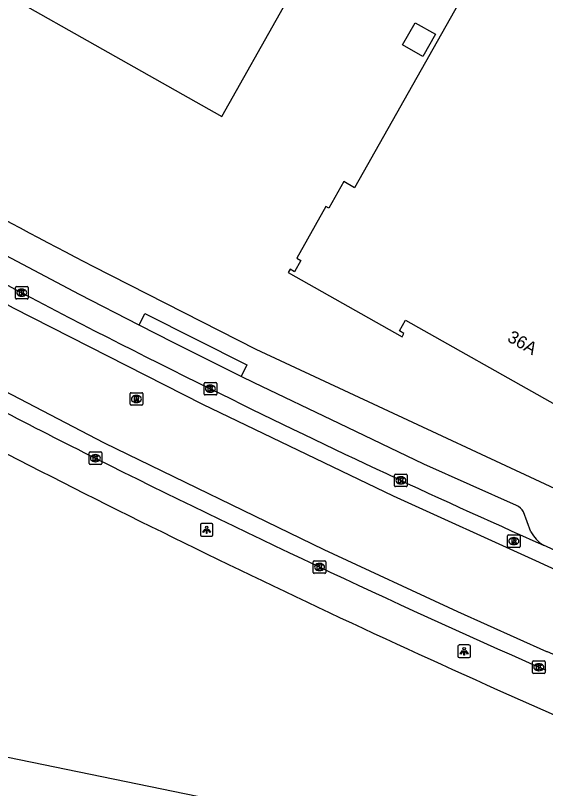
# Model space of a CAD drawing. Extents: x 157692 to 159670, y 381454 to 383289.
# Drawn here: x 158086.3 to 158128.6, y 382784.5 to 382846.1 of the extents above; entities that cross this region are included whole.
import ezdxf

# ---------------------------------------------------------------- set-up
doc = ezdxf.new("R2010")
doc.units = 0
for name, color, linetype in [('IMGEO_Kolk', 7, 'Continuous'), ('IMGEO_Lage_trafo', 7, 'Continuous'), ('IMGEO_Lichtpunt', 7, 'Continuous'), ('IMGEO_Pand', 7, 'Continuous'), ('IMGEO_Pand_nummerreeks', 7, 'Continuous'), ('IMGEO_Rijbaan_lokaal_gesloten', 7, 'Continuous'), ('IMGEO_Rioolput', 7, 'Continuous'), ('IMGEO_Voetpad_open', 7, 'Continuous')]:
    doc.layers.add(name, color=color, linetype=linetype)

msp = doc.modelspace()

# ---------------------------------------------------------------- linework, layer by layer
at = {"layer": 'IMGEO_Kolk'}
for p, q in [((158086.342, 382823.554), (158086.342, 382824.406)), ((158086.417, 382824.48), (158087.269, 382824.48)), ((158087.343, 382824.406), (158087.343, 382823.554)), ((158086.83, 382824.26), (158086.855, 382824.26)), ((158087.269, 382823.48), (158086.417, 382823.48)), ((158086.853, 382823.7), (158086.828, 382823.7)), ((158101.372, 382815.913), (158101.372, 382816.765)), ((158101.447, 382816.839), (158102.299, 382816.839)), ((158101.86, 382816.619), (158101.885, 382816.619)), ((158102.373, 382816.765), (158102.373, 382815.913)), ((158102.299, 382815.839), (158101.447, 382815.839)), ((158101.883, 382816.059), (158101.858, 382816.059)), ((158092.209, 382810.382), (158092.209, 382811.234)), ((158092.284, 382811.308), (158093.136, 382811.308)), ((158092.697, 382811.088), (158092.722, 382811.088)), ((158093.21, 382811.234), (158093.21, 382810.382)), ((158093.136, 382810.308), (158092.284, 382810.308)), ((158092.72, 382810.528), (158092.695, 382810.528)), ((158116.546, 382808.615), (158116.546, 382809.467)), ((158116.621, 382809.541), (158117.473, 382809.541)), ((158117.034, 382809.321), (158117.059, 382809.321)), ((158117.547, 382809.467), (158117.547, 382808.615)), ((158117.473, 382808.541), (158116.621, 382808.541)), ((158117.057, 382808.761), (158117.032, 382808.761)), ((158110.067, 382801.715), (158110.067, 382802.567)), ((158110.142, 382802.641), (158110.994, 382802.641)), ((158110.555, 382802.421), (158110.58, 382802.421)), ((158111.068, 382802.567), (158111.068, 382801.715)), ((158110.994, 382801.641), (158110.142, 382801.641)), ((158110.578, 382801.861), (158110.553, 382801.861)), ((158127.53, 382793.741), (158127.53, 382794.593)), ((158127.605, 382794.667), (158128.457, 382794.667)), ((158128.018, 382794.447), (158128.043, 382794.447)), ((158128.531, 382794.593), (158128.531, 382793.741)), ((158128.457, 382793.667), (158127.605, 382793.667)), ((158128.041, 382793.887), (158128.016, 382793.887))]:
    msp.add_line(p, q, dxfattribs=at)
for points in [[(158086.342, 382823.554), (158086.342, 382824.406)], [(158086.417, 382824.48), (158087.269, 382824.48)], [(158087.343, 382824.406), (158087.343, 382823.554)], [(158086.663, 382824.18), (158086.786, 382824.18), (158086.786, 382824.029), (158086.916, 382824.18), (158087.08, 382824.18), (158086.934, 382824.029), (158087.087, 382823.78), (158086.935, 382823.78), (158086.85, 382823.944), (158086.786, 382823.877), (158086.786, 382823.78), (158086.663, 382823.78), (158086.663, 382824.18)], [(158087.269, 382823.48), (158086.417, 382823.48)], [(158101.372, 382815.913), (158101.372, 382816.765)], [(158101.447, 382816.839), (158102.299, 382816.839)], [(158101.693, 382816.539), (158101.816, 382816.539), (158101.816, 382816.388), (158101.946, 382816.539), (158102.11, 382816.539), (158101.964, 382816.388), (158102.117, 382816.139), (158101.965, 382816.139), (158101.88, 382816.303), (158101.816, 382816.236), (158101.816, 382816.139), (158101.693, 382816.139), (158101.693, 382816.539)], [(158102.373, 382816.765), (158102.373, 382815.913)], [(158102.299, 382815.839), (158101.447, 382815.839)], [(158092.209, 382810.382), (158092.209, 382811.234)], [(158092.284, 382811.308), (158093.136, 382811.308)], [(158092.53, 382811.008), (158092.653, 382811.008), (158092.653, 382810.857), (158092.783, 382811.008), (158092.947, 382811.008), (158092.801, 382810.857), (158092.954, 382810.608), (158092.802, 382810.608), (158092.717, 382810.772), (158092.653, 382810.705), (158092.653, 382810.608), (158092.53, 382810.608), (158092.53, 382811.008)], [(158093.21, 382811.234), (158093.21, 382810.382)], [(158093.136, 382810.308), (158092.284, 382810.308)], [(158116.546, 382808.615), (158116.546, 382809.467)], [(158116.621, 382809.541), (158117.473, 382809.541)], [(158116.867, 382809.241), (158116.99, 382809.241), (158116.99, 382809.09), (158117.12, 382809.241), (158117.284, 382809.241), (158117.138, 382809.09), (158117.291, 382808.841), (158117.139, 382808.841), (158117.054, 382809.005), (158116.99, 382808.938), (158116.99, 382808.841), (158116.867, 382808.841), (158116.867, 382809.241)], [(158117.547, 382809.467), (158117.547, 382808.615)], [(158117.473, 382808.541), (158116.621, 382808.541)], [(158110.067, 382801.715), (158110.067, 382802.567)], [(158110.142, 382802.641), (158110.994, 382802.641)], [(158110.388, 382802.341), (158110.511, 382802.341), (158110.511, 382802.19), (158110.641, 382802.341), (158110.805, 382802.341), (158110.659, 382802.19), (158110.812, 382801.941), (158110.66, 382801.941), (158110.575, 382802.105), (158110.511, 382802.038), (158110.511, 382801.941), (158110.388, 382801.941), (158110.388, 382802.341)], [(158111.068, 382802.567), (158111.068, 382801.715)], [(158110.994, 382801.641), (158110.142, 382801.641)], [(158127.53, 382793.741), (158127.53, 382794.593)], [(158127.605, 382794.667), (158128.457, 382794.667)], [(158127.851, 382794.367), (158127.974, 382794.367), (158127.974, 382794.216), (158128.104, 382794.367), (158128.268, 382794.367), (158128.122, 382794.216), (158128.275, 382793.967), (158128.123, 382793.967), (158128.038, 382794.131), (158127.974, 382794.064), (158127.974, 382793.967), (158127.851, 382793.967), (158127.851, 382794.367)], [(158128.531, 382794.593), (158128.531, 382793.741)], [(158128.457, 382793.667), (158127.605, 382793.667)]]:
    msp.add_lwpolyline(points, dxfattribs=at)
for centre, start, end in [((158086.419, 382824.404), 91.55205, 178.44795), ((158086.419, 382824.404), 91.55205, 178.44795), ((158087.267, 382824.404), 1.55205, 88.44795), ((158087.267, 382824.404), 1.55205, 88.44795), ((158086.419, 382823.556), 181.55205, 268.44795), ((158086.419, 382823.556), 181.55205, 268.44795), ((158087.267, 382823.556), 271.55205, 358.44795), ((158087.267, 382823.556), 271.55205, 358.44795), ((158101.449, 382816.763), 91.55205, 178.44795), ((158101.449, 382816.763), 91.55205, 178.44795), ((158102.297, 382816.763), 1.55205, 88.44795), ((158102.297, 382816.763), 1.55205, 88.44795), ((158101.449, 382815.915), 181.55205, 268.44795), ((158101.449, 382815.915), 181.55205, 268.44795), ((158102.297, 382815.915), 271.55205, 358.44795), ((158102.297, 382815.915), 271.55205, 358.44795), ((158092.286, 382811.232), 91.55205, 178.44795), ((158092.286, 382811.232), 91.55205, 178.44795), ((158093.134, 382811.232), 1.55205, 88.44795), ((158093.134, 382811.232), 1.55205, 88.44795), ((158092.286, 382810.384), 181.55205, 268.44795), ((158092.286, 382810.384), 181.55205, 268.44795), ((158093.134, 382810.384), 271.55205, 358.44795), ((158093.134, 382810.384), 271.55205, 358.44795), ((158116.623, 382809.465), 91.55205, 178.44795), ((158116.623, 382809.465), 91.55205, 178.44795), ((158117.471, 382809.465), 1.55205, 88.44795), ((158117.471, 382809.465), 1.55205, 88.44795), ((158116.623, 382808.617), 181.55205, 268.44795), ((158116.623, 382808.617), 181.55205, 268.44795), ((158117.471, 382808.617), 271.55205, 358.44795), ((158117.471, 382808.617), 271.55205, 358.44795), ((158110.144, 382802.565), 91.55205, 178.44795), ((158110.144, 382802.565), 91.55205, 178.44795), ((158110.992, 382802.565), 1.55205, 88.44795), ((158110.992, 382802.565), 1.55205, 88.44795), ((158110.144, 382801.717), 181.55205, 268.44795), ((158110.144, 382801.717), 181.55205, 268.44795), ((158110.992, 382801.717), 271.55205, 358.44795), ((158110.992, 382801.717), 271.55205, 358.44795), ((158127.607, 382794.591), 91.55205, 178.44795), ((158127.607, 382794.591), 91.55205, 178.44795), ((158128.455, 382794.591), 1.55205, 88.44795), ((158128.455, 382794.591), 1.55205, 88.44795), ((158127.607, 382793.743), 181.55205, 268.44795), ((158127.607, 382793.743), 181.55205, 268.44795), ((158128.455, 382793.743), 271.55205, 358.44795), ((158128.455, 382793.743), 271.55205, 358.44795)]:
    msp.add_arc(centre, 0.0765, start, end, dxfattribs=at)
for centre, major_axis, ratio, start_param, end_param in [((158086.829, 382823.98), (-0.387, 0.002), 0.722429, 4.712389, 7.853982), ((158086.854, 382823.98), (-0.39, 0.002), 0.717154, 1.570796, 4.712389), ((158101.859, 382816.339), (-0.387, 0.002), 0.722429, 4.712389, 7.853982), ((158101.884, 382816.339), (-0.39, 0.002), 0.717154, 1.570796, 4.712389), ((158092.696, 382810.808), (-0.387, 0.002), 0.722429, 4.712389, 7.853982), ((158092.721, 382810.808), (-0.39, 0.002), 0.717154, 1.570796, 4.712389), ((158117.033, 382809.041), (-0.387, 0.002), 0.722429, 4.712389, 7.853982), ((158117.058, 382809.041), (-0.39, 0.002), 0.717154, 1.570796, 4.712389), ((158110.554, 382802.141), (-0.387, 0.002), 0.722429, 4.712389, 7.853982), ((158110.579, 382802.141), (-0.39, 0.002), 0.717154, 1.570796, 4.712389), ((158128.017, 382794.167), (-0.387, 0.002), 0.722429, 4.712389, 7.853982), ((158128.042, 382794.167), (-0.39, 0.002), 0.717154, 1.570796, 4.712389)]:
    msp.add_ellipse(centre, major_axis=major_axis, ratio=ratio, start_param=start_param, end_param=end_param, dxfattribs=at)
at = {"layer": 'IMGEO_Lage_trafo'}
msp.add_lwpolyline([(158118.179, 382845.478), (158119.8, 382844.565), (158118.803, 382842.797), (158117.182, 382843.71), (158118.179, 382845.478)], dxfattribs=at)
at = {"layer": 'IMGEO_Lichtpunt'}
for p, q in [((158101.075, 382805.506), (158101.075, 382804.699)), ((158101.075, 382805.506), (158101.075, 382804.699)), ((158101.977, 382805.601), (158101.169, 382805.601)), ((158101.977, 382805.601), (158101.169, 382805.601)), ((158102.071, 382804.699), (158102.071, 382805.506)), ((158102.071, 382804.699), (158102.071, 382805.506)), ((158101.169, 382804.605), (158101.977, 382804.605)), ((158101.169, 382804.605), (158101.977, 382804.605)), ((158121.59, 382795.841), (158121.59, 382795.034)), ((158121.59, 382795.841), (158121.59, 382795.034)), ((158122.492, 382795.936), (158121.684, 382795.936)), ((158122.492, 382795.936), (158121.684, 382795.936)), ((158122.586, 382795.034), (158122.586, 382795.841)), ((158122.586, 382795.034), (158122.586, 382795.841)), ((158121.684, 382794.94), (158122.492, 382794.94)), ((158121.684, 382794.94), (158122.492, 382794.94))]:
    msp.add_line(p, q, dxfattribs=at)
for points in [[(158101.449, 382805.17), (158101.488, 382805.142), (158101.3, 382804.88), (158101.262, 382804.907), (158101.449, 382805.17)], [(158101.551, 382805.122), (158101.598, 382805.122), (158101.598, 382804.8), (158101.551, 382804.8), (158101.551, 382805.122)], [(158101.661, 382805.142), (158101.699, 382805.169), (158101.886, 382804.907), (158101.847, 382804.879), (158101.661, 382805.142)], [(158121.964, 382795.505), (158122.003, 382795.477), (158121.815, 382795.215), (158121.777, 382795.242), (158121.964, 382795.505)], [(158122.066, 382795.457), (158122.113, 382795.457), (158122.113, 382795.135), (158122.066, 382795.135), (158122.066, 382795.457)], [(158122.176, 382795.477), (158122.214, 382795.504), (158122.401, 382795.242), (158122.362, 382795.214), (158122.176, 382795.477)]]:
    msp.add_lwpolyline(points, dxfattribs=at)
for centre in [(158101.574, 382805.304), (158122.089, 382795.639)]:
    msp.add_circle(centre, 0.0994, dxfattribs=at)
for centre, start, end in [((158101.169, 382805.506), 90, 180), ((158101.169, 382805.506), 90, 180), ((158101.977, 382805.506), 0, 90), ((158101.977, 382805.506), 0, 90), ((158101.169, 382804.699), 180, 270), ((158101.169, 382804.699), 180, 270), ((158101.977, 382804.699), 270, 0), ((158101.977, 382804.699), 270, 360), ((158121.684, 382795.841), 90, 180), ((158121.684, 382795.841), 90, 180), ((158122.492, 382795.841), 0, 90), ((158122.492, 382795.841), 0, 90), ((158121.684, 382795.034), 180, 270), ((158121.684, 382795.034), 180, 270), ((158122.492, 382795.034), 270, 0), ((158122.492, 382795.034), 270, 360)]:
    msp.add_arc(centre, 0.0946, start, end, dxfattribs=at)
at = {"layer": 'IMGEO_Pand'}
for points in [[(158076.13, 382853.045), (158102.778, 382838.008), (158122.441, 382872.854)], [(158122.441, 382872.854), (158132.855, 382866.887), (158113.362, 382832.341), (158112.496, 382832.829), (158111.302, 382830.713), (158111.059, 382830.851), (158108.747, 382826.73), (158109.078, 382826.544), (158108.573, 382825.646), (158108.216, 382825.847), (158108.064, 382825.577), (158117.135, 382820.47), (158117.287, 382820.74), (158116.929, 382820.941), (158117.415, 382821.803), (158140.398, 382808.833)], [(158064.858, 382743.158), (158065.009, 382743.893), (158065.049, 382744.088), (158066.652, 382751.877), (158070.97, 382772.966), (158065.734, 382774.048), (158067.998, 382785.097), (158073.252, 382784.004), (158074.334, 382789.347), (158144.219, 382774.976), (158141.976, 382764.406), (158173.817, 382757.927), (158165.052, 382715.563), (158167.154, 382715.126), (158167.707, 382715.011), (158163.216, 382693.402), (158162.512, 382693.548), (158160.573, 382693.951), (158138.948, 382588.16)]]:
    msp.add_lwpolyline(points, dxfattribs=at)
at = {"layer": 'IMGEO_Rijbaan_lokaal_gesloten'}
for points in [[(158286.514, 382753.477), (158260.379, 382758.975), (158254.227, 382760.339), (158248.354, 382761.725), (158242.501, 382763.187), (158236.667, 382764.728), (158230.854, 382766.346), (158224.966, 382768.069), (158212.034, 382771.752), (158186.42, 382779.71), (158168.446, 382786.031), (158150.232, 382793.099), (158135.179, 382799.369), (158132.175, 382800.62), (158132.064, 382800.666), (158127.783, 382802.635), (158116.454, 382807.771), (158101.276, 382815.071), (158086.186, 382822.743), (158068.81, 382832.394), (158056.432, 382839.751), (158045.401, 382846.414), (158021.35, 382861.883), (158020.199, 382862.608)], [(158028.335, 382849.775), (158037.048, 382844.256), (158044.179, 382839.822), (158049.045, 382836.833), (158059.605, 382830.531), (158078.049, 382820.024), (158093.411, 382812.024), (158110.915, 382803.527), (158121.561, 382798.603), (158128.648, 382795.428), (158128.687, 382795.41), (158132.24, 382793.865), (158134.794, 382792.768), (158138.633, 382791.144), (158146.804, 382787.774), (158153.039, 382785.283), (158159.791, 382782.622), (158168.478, 382779.412), (158178.655, 382775.82), (158186.872, 382773.054), (158193.951, 382770.766), (158206.629, 382766.928)], [(158132.713, 382801.912), (158132.364, 382802.069), (158128.395, 382803.894)], [(158128.604, 382793.917), (158128.34, 382794.033), (158128.075, 382794.149)]]:
    msp.add_lwpolyline(points, dxfattribs=at)
for centre, radius, start, end in [((158320.346, 383264.713), 498.769, 239.8074, 244.02209), ((158311.885, 383250.337), 491.144, 241.48225, 243.5017), ((158390.4, 383396.792), 648.209, 243.569376, 246.159118), ((158464.988, 383555.173), 832.267, 243.432201, 246.120567)]:
    msp.add_arc(centre, radius, start, end, dxfattribs=at)
at = {"layer": 'IMGEO_Rioolput'}
for p, q in [((158095.475, 382815.096), (158095.475, 382815.948)), ((158095.55, 382816.022), (158096.402, 382816.022)), ((158095.963, 382815.802), (158095.988, 382815.802)), ((158096.476, 382815.948), (158096.476, 382815.096)), ((158095.986, 382815.242), (158095.961, 382815.242)), ((158096.402, 382815.022), (158095.55, 382815.022)), ((158125.617, 382804.706), (158126.469, 382804.706)), ((158125.542, 382803.78), (158125.542, 382804.632)), ((158126.03, 382804.486), (158126.055, 382804.486)), ((158126.543, 382804.632), (158126.543, 382803.78)), ((158126.469, 382803.706), (158125.617, 382803.706)), ((158126.053, 382803.926), (158126.028, 382803.926))]:
    msp.add_line(p, q, dxfattribs=at)
for points in [[(158095.475, 382815.096), (158095.475, 382815.948)], [(158095.55, 382816.022), (158096.402, 382816.022)], [(158096.476, 382815.948), (158096.476, 382815.096)], [(158096.064, 382815.72), (158095.812, 382815.722), (158095.812, 382815.322)], [(158095.812, 382815.322), (158095.936, 382815.322), (158095.936, 382815.484), (158095.947, 382815.484)], [(158095.99, 382815.641), (158095.936, 382815.641), (158095.936, 382815.56)], [(158095.936, 382815.56), (158095.988, 382815.56)], [(158095.994, 382815.455), (158096.065, 382815.322), (158096.205, 382815.322), (158096.14, 382815.448)], [(158096.402, 382815.022), (158095.55, 382815.022)], [(158125.617, 382804.706), (158126.469, 382804.706)], [(158125.542, 382803.78), (158125.542, 382804.632)], [(158126.131, 382804.404), (158125.879, 382804.406), (158125.879, 382804.006)], [(158125.879, 382804.006), (158126.003, 382804.006), (158126.003, 382804.168), (158126.014, 382804.168)], [(158126.057, 382804.325), (158126.003, 382804.325), (158126.003, 382804.244)], [(158126.003, 382804.244), (158126.055, 382804.244)], [(158126.061, 382804.139), (158126.132, 382804.006), (158126.272, 382804.006), (158126.207, 382804.132)], [(158126.543, 382804.632), (158126.543, 382803.78)], [(158126.469, 382803.706), (158125.617, 382803.706)]]:
    msp.add_lwpolyline(points, dxfattribs=at)
for centre, radius, start, end in [((158095.552, 382815.946), 0.0765, 91.55205, 178.44795), ((158095.552, 382815.946), 0.0765, 91.55205, 178.44795), ((158096.4, 382815.946), 0.0765, 1.55205, 88.44795), ((158096.4, 382815.946), 0.0765, 1.55205, 88.44795), ((158095.946, 382815.431), 0.0533, 26.02933, 88.69889), ((158095.972, 382815.749), 0.19, 274.7715, 282.96867), ((158095.996, 382815.545), 0.0964, 77.00612, 93.18647), ((158096.01, 382815.602), 0.0378, 276.66336, 79.67722), ((158096.063, 382815.61), 0.109, 350.36119, 89.41601), ((158096.061, 382815.61), 0.112, 277.58423, 350.98172), ((158096.045, 382815.395), 0.108, 29.51342, 73.79051), ((158095.552, 382815.098), 0.0765, 181.55205, 268.44795), ((158095.552, 382815.098), 0.0765, 181.55205, 268.44795), ((158096.4, 382815.098), 0.0765, 271.55205, 358.44795), ((158096.4, 382815.098), 0.0765, 271.55205, 358.44795), ((158125.619, 382804.63), 0.0765, 91.55205, 178.44795), ((158125.619, 382804.63), 0.0765, 91.55205, 178.44795), ((158126.467, 382804.63), 0.0765, 1.55205, 88.44795), ((158126.467, 382804.63), 0.0765, 1.55205, 88.44795), ((158126.013, 382804.115), 0.0533, 26.02933, 88.69889), ((158126.039, 382804.433), 0.19, 274.7715, 282.96867), ((158126.063, 382804.229), 0.0964, 77.00612, 93.18647), ((158126.077, 382804.286), 0.0378, 276.66336, 79.67722), ((158126.13, 382804.294), 0.109, 350.36119, 89.41601), ((158126.128, 382804.294), 0.112, 277.58423, 350.98172), ((158126.112, 382804.079), 0.108, 29.51342, 73.79051), ((158125.619, 382803.782), 0.0765, 181.55205, 268.44795), ((158125.619, 382803.782), 0.0765, 181.55205, 268.44795), ((158126.467, 382803.782), 0.0765, 271.55205, 358.44795), ((158126.467, 382803.782), 0.0765, 271.55205, 358.44795)]:
    msp.add_arc(centre, radius, start, end, dxfattribs=at)
for centre, major_axis, ratio, start_param, end_param in [((158095.962, 382815.522), (-0.387, 0.002), 0.722429, 4.712389, 7.853982), ((158095.987, 382815.522), (-0.39, 0.002), 0.717154, 1.570796, 4.712389), ((158126.029, 382804.206), (-0.387, 0.002), 0.722429, 4.712389, 7.853982), ((158126.054, 382804.206), (-0.39, 0.002), 0.717154, 1.570796, 4.712389)]:
    msp.add_ellipse(centre, major_axis=major_axis, ratio=ratio, start_param=start_param, end_param=end_param, dxfattribs=at)
at = {"layer": 'IMGEO_Voetpad_open'}
for points in [[(158096.186, 382821.403), (158091.449, 382823.826), (158084.635, 382827.414)], [(158092.511, 382826.086), (158105.484, 382819.486), (158137.863, 382804.409)], [(158096.186, 382821.403), (158096.649, 382822.335), (158104.784, 382818.251), (158104.321, 382817.32)], [(158104.321, 382817.32), (158098.956, 382819.986), (158096.186, 382821.403)], [(158126.257, 382807.046), (158118.868, 382810.337), (158112.129, 382813.57), (158105.351, 382816.808), (158104.321, 382817.32)], [(158127.408, 382804.933), (158126.812, 382806.528)]]:
    msp.add_lwpolyline(points, dxfattribs=at)
for centre, radius, start, end in [((158393.942, 383404.409), 652.165, 240.169003, 242.470793), ((158450.81, 383521.255), 798.487, 241.801034, 246.323127), ((158125.742, 382805.938), 1.221, 28.8684, 65.08147), ((158129.832, 382806.248), 2.758, 208.47141, 238.58809)]:
    msp.add_arc(centre, radius, start, end, dxfattribs=at)

# ---------------------------------------------------------------- texts
at = {"layer": 'IMGEO_Pand_nummerreeks'}
msp.add_text('36A', height=1, rotation=330.56143, dxfattribs=at).set_placement((158125.452, 382820.162))

doc.saveas('drawing.dxf')
